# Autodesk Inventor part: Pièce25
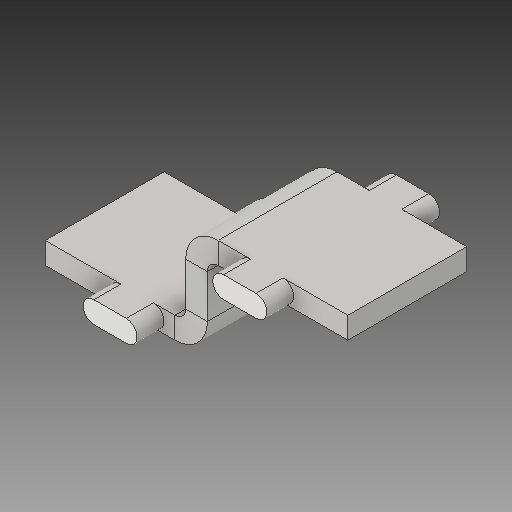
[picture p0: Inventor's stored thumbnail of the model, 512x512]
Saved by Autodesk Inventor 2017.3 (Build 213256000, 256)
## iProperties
Created: 2007-12
Part Number: Pièce25
Material: Générique
Document SubType Name: Modeling
Designer: ficho
Density: 1 g/cm^3
Appearance: Par défaut
Author: ficho
Sending System: SolidWorks 2009
Last Author: christophe
Last Saved: 2011-02-10
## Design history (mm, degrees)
extrude "Extrusion4"
node "Solide1"
